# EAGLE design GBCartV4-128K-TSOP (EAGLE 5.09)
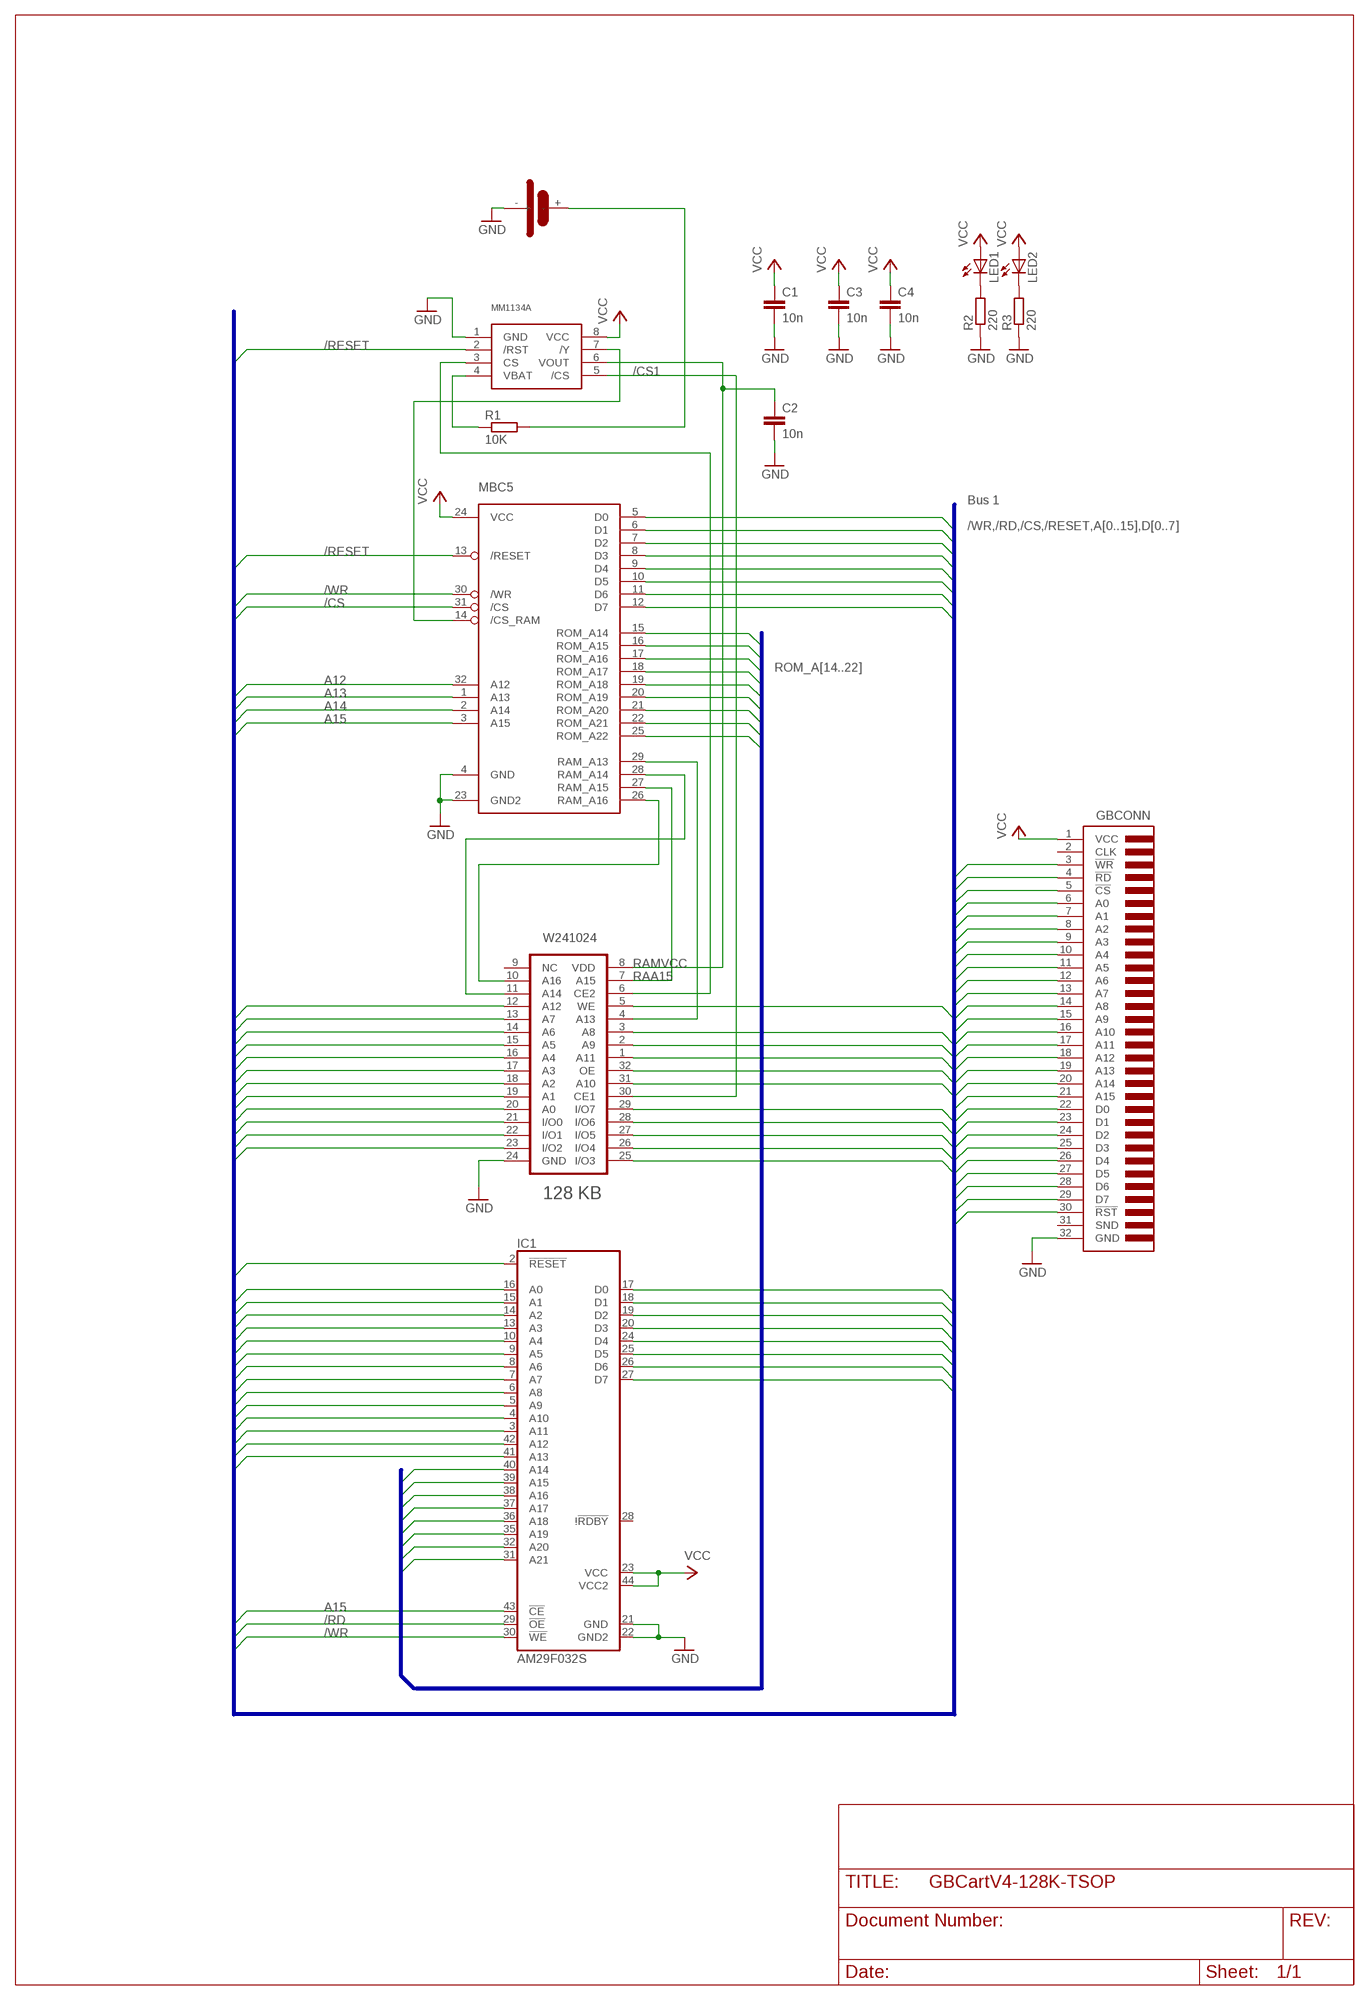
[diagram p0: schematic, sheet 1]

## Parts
C1  10n  C-EUC0805  [C0805]
C2  10n  C-EUC0805  [C0805]
C3  10n  C-EUC0805  [C0805]
C4  10n  C-EUC0805  [C0805]
GBCONN  GBCART-FULL  [GBCART]
IC1  AM29F032S  [SO44]
IC2  MBC5  [TQFP32-08]
IC3  W241024AT  [TSOP32]
IC4  MM1134A  [SOP08]
LED1  LEDCHIPLED_1206  [CHIPLED_1206]
LED2  LEDCHIPLED_1206  [CHIPLED_1206]
R1  10K  R-EU_R0805  [R0805]
R2  220  R-EU_R0805  [R0805]
R3  220  R-EU_R0805  [R0805]
U$1  CR1616  [CR1616]

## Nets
/CS [Signal]: GBCONN.5(!CS) IC2.31(/CS)
/CS1 [Signal]: IC3.30(CE1) IC4.5(/CS)
/CS2: IC3.6(CE2) IC4.3(CS)
/RD [Signal]: GBCONN.4(!RD) IC1.29(!OE) IC3.32(OE)
/RESET [Signal]: GBCONN.30(!RST) IC1.2(!RESET) IC2.13(/RESET) IC4.2(/RST)
/WR [Signal]: GBCONN.3(!WR) IC1.30(!WE) IC2.30(/WR) IC3.5(WE)
A0 [Signal]: GBCONN.6(A0) IC1.16(A0) IC3.20(A0)
A1 [Signal]: GBCONN.7(A1) IC1.15(A1) IC3.19(A1)
A2 [Signal]: GBCONN.8(A2) IC1.14(A2) IC3.18(A2)
A3 [Signal]: GBCONN.9(A3) IC1.13(A3) IC3.17(A3)
A4 [Signal]: GBCONN.10(A4) IC1.10(A4) IC3.16(A4)
A5 [Signal]: GBCONN.11(A5) IC1.9(A5) IC3.15(A5)
A6 [Signal]: GBCONN.12(A6) IC1.8(A6) IC3.14(A6)
A7 [Signal]: GBCONN.13(A7) IC1.7(A7) IC3.13(A7)
A8 [Signal]: GBCONN.14(A8) IC1.6(A8) IC3.3(A8)
A9 [Signal]: GBCONN.15(A9) IC1.5(A9) IC3.2(A9)
A10 [Signal]: GBCONN.16(A10) IC1.4(A10) IC3.31(A10)
A11 [Signal]: GBCONN.17(A11) IC1.3(A11) IC3.1(A11)
A12 [Signal]: GBCONN.18(A12) IC1.42(A12) IC2.32(A12) IC3.12(A12)
A13 [Signal]: GBCONN.19(A13) IC1.41(A13) IC2.1(A13)
A14 [Signal]: GBCONN.20(A14) IC2.2(A14)
A15 [Signal]: GBCONN.21(A15) IC1.43(!CE) IC2.3(A15)
D0 [Signal]: GBCONN.22(D0) IC1.17(D0) IC2.5(D0) IC3.21(I/O0)
D1 [Signal]: GBCONN.23(D1) IC1.18(D1) IC2.6(D1) IC3.22(I/O1)
D2 [Signal]: GBCONN.24(D2) IC1.19(D2) IC2.7(D2) IC3.23(I/O2)
D3 [Signal]: GBCONN.25(D3) IC1.20(D3) IC2.8(D3) IC3.25(I/O3)
D4 [Signal]: GBCONN.26(D4) IC1.24(D4) IC2.9(D4) IC3.26(I/O4)
D5 [Signal]: GBCONN.27(D5) IC1.25(D5) IC2.10(D5) IC3.27(I/O5)
D6 [Signal]: GBCONN.28(D6) IC1.26(D6) IC2.11(D6) IC3.28(I/O6)
D7 [Signal]: GBCONN.29(D7) IC1.27(D7) IC2.12(D7) IC3.29(I/O7)
GND: C1.2 C2.2 C3.2 C4.2 GBCONN.32(GND) IC1.21(GND) IC1.22(GND2) IC2.4(GND) IC2.23(GND2) IC3.24(GND) IC4.1(GND) R2.1 R3.1 U$1.-
N$3: LED1.C R2.2
N$4: IC4.4(VBAT) R1.1
N$5: R1.2 U$1.+
N$6: LED2.C R3.2
N$12 [Signal]: IC2.14(/CS_RAM) IC4.7(/Y)
RAA13: IC2.29(RAM_A13) IC3.4(A13)
RAA14: IC2.28(RAM_A14) IC3.11(A14)
RAA15: IC2.27(RAM_A15) IC3.7(A15)
RAA16: IC2.26(RAM_A16) IC3.10(A16)
RAMVCC: C2.1 IC3.8(VDD) IC4.6(VOUT)
ROM_A14 [Signal]: IC1.40(A14) IC2.15(ROM_A14)
ROM_A15 [Signal]: IC1.39(A15) IC2.16(ROM_A15)
ROM_A16 [Signal]: IC1.38(A16) IC2.17(ROM_A16)
ROM_A17 [Signal]: IC1.37(A17) IC2.18(ROM_A17)
ROM_A18 [Signal]: IC1.36(A18) IC2.19(ROM_A18)
ROM_A19 [Signal]: IC1.35(A19) IC2.20(ROM_A19)
ROM_A20 [Signal]: IC1.32(A20) IC2.21(ROM_A20)
ROM_A21 [Signal]: IC1.31(A21) IC2.22(ROM_A21)
ROM_A22: IC2.25(ROM_A22)
VCC: C1.1 C3.1 C4.1 GBCONN.1(VCC) IC1.23(VCC) IC1.44(VCC2) IC2.24(VCC) IC4.8(VCC) LED1.A LED2.A
Unconnected: GBCONN.2(CLK) GBCONN.31(SND) IC1.28(!!RDBY) IC3.9(NC)

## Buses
/WR,/RD,/CS,/RESET,A[0..15],D[0..7]
ROM_A[14..22]

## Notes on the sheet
- Bus 1

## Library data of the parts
C1-C4 = rcl:C-EU: CAPACITOR, European symbol
GBCONN = gameboy:GBCART
IC1 = gameboy:AM29F032S: 4-Megabit FLASH MEMORY (512 K x 8 bit/256 K x 16 Bit) 5 V-only
IC2 = gameboy:MBC5
IC3 = gameboy:W241024AT
IC4 = gameboy:MM1134A
LED1 LED2 = led:LED: LED
R1-R3 = rcl:R-EU_: RESISTOR, European symbol
U$1 = gameboy:CR1616

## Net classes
0 Supply: width 0.254 mm, clearance 0.254 mm
1 Signal: width 0.15 mm, clearance 0.15 mm

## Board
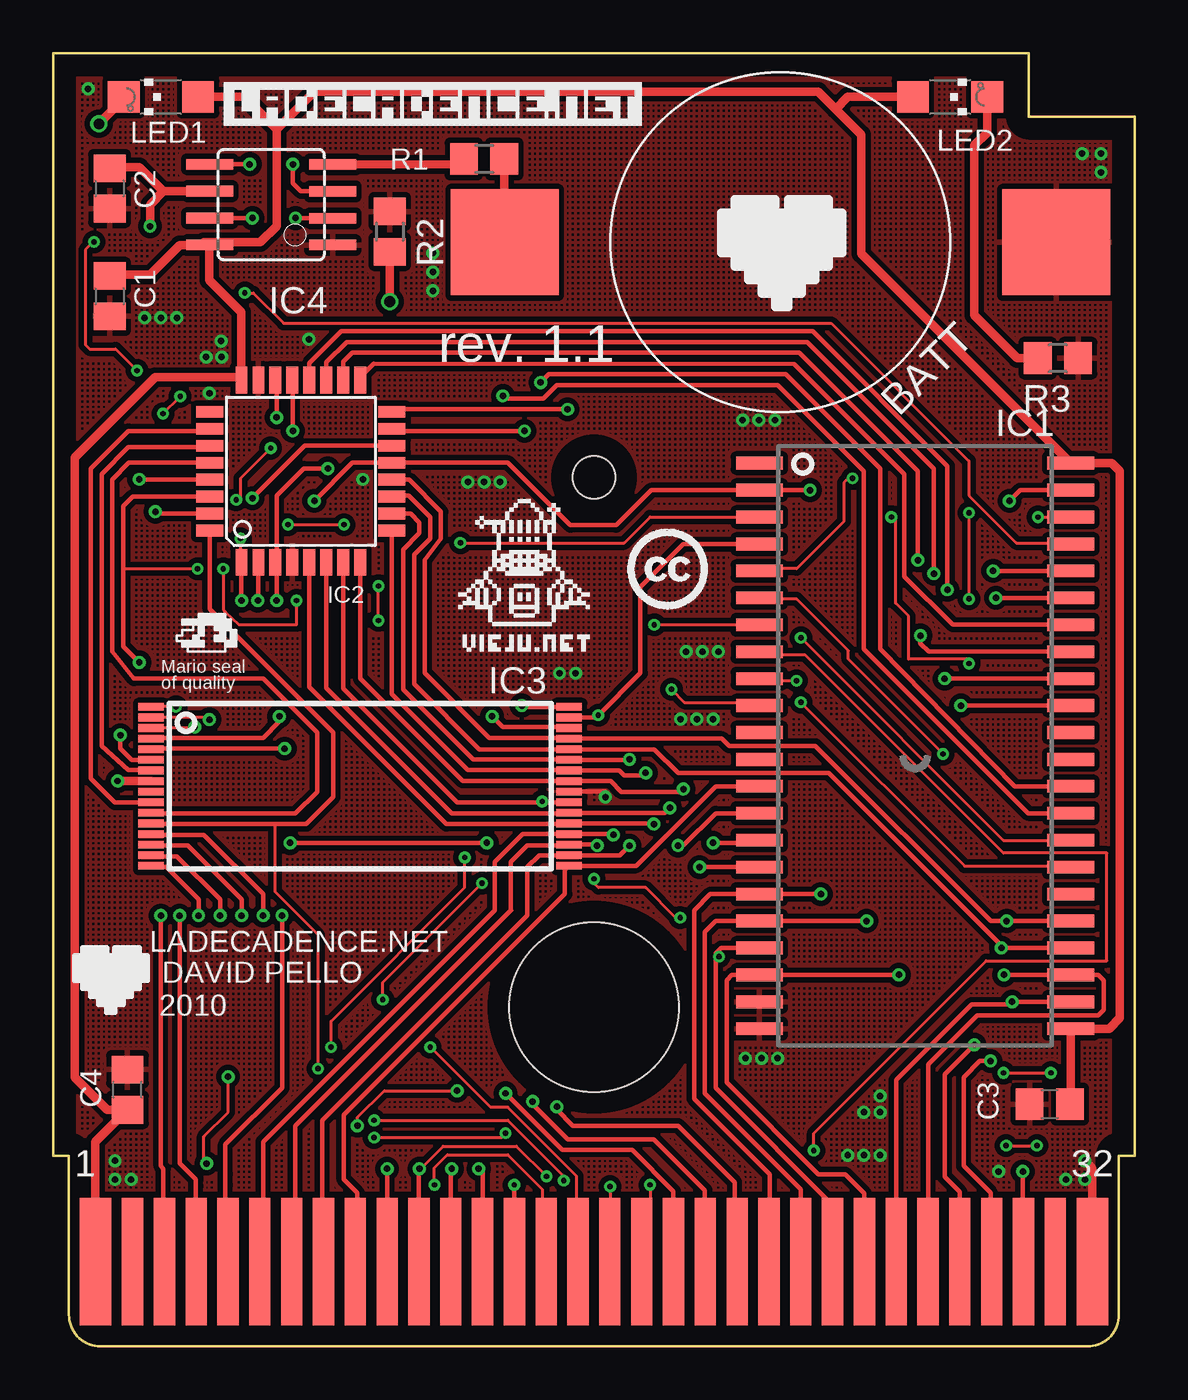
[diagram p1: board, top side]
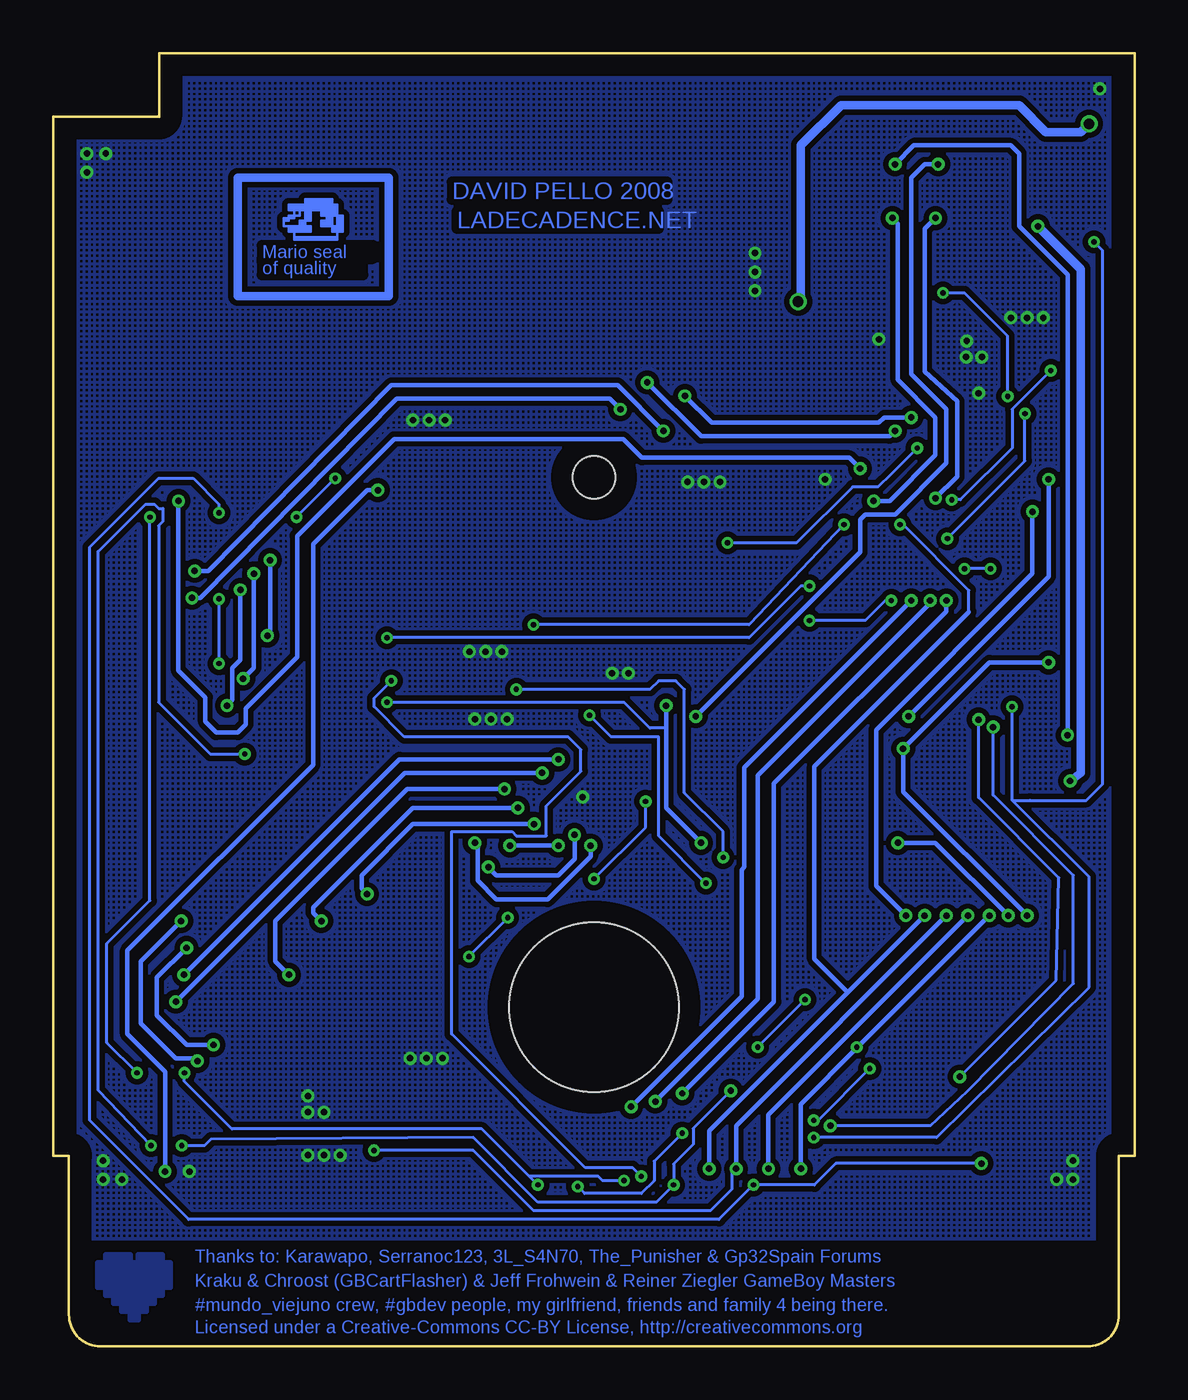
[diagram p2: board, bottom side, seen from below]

Size 51 x 61 mm. Coordinates in mm from the lower left corner, seen from the top.
Copper layers (1*16): Top 0.035mm / dielectric 1.5mm / Bottom 0.035mm
Design rules "default *": minimum track width 0.15mm, minimum drill 0.25mm, track to track 0.15mm, track to pad 0.15mm, pad to pad 0.15mm, via to via 0.15mm, smd to smd 8mil, copper to edge 40mil, drill to drill 8mil, minimum pad ring 6mil, minimum via ring 6mil, stop-mask expansion 4mil, vias tented up to drill 0mil, thermal gap 10mil

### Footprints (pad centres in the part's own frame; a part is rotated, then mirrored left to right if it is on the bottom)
C0805 = smd 1.3 x 1.5: 1 -0.95,0; 2 0.95,0
GBCART = smd 1.5 x 6: 1 -23.4,-25.21; 32 23.6,-25.21 | smd 1 x 6: 2 -21.65,-25.21; 3 -20.15,-25.21; 4 -18.65,-25.21; 5 -17.15,-25.21; 6 -15.65,-25.21; 7 -14.15,-25.21; 8 -12.65,-25.21; 9 -11.15,-25.21; 10 -9.65,-25.21; 11 -8.15,-25.21; 12 -6.65,-25.21; 13 -5.15,-25.21; 14 -3.65,-25.21; 15 -2.15,-25.21; 16 -0.65,-25.21; 17 0.85,-25.21; 18 2.35,-25.21; 19 3.85,-25.21; 20 5.35,-25.21; 21 6.85,-25.21; 22 8.35,-25.21; 23 9.85,-25.21; 24 11.35,-25.21; 25 12.85,-25.21; 26 14.35,-25.21; 27 15.85,-25.21; 28 17.35,-25.21; 29 18.85,-25.21; 30 20.35,-25.21; 31 21.85,-25.21 | hole 8: 0.1,-13.21 | hole 2: 0.1,11.79
SO44 = smd 0.6 x 2.2: 1 -13.335,-7.34; 2 -12.065,-7.34; 3 -10.795,-7.34; 4 -9.525,-7.34; 5 -8.255,-7.34; 6 -6.985,-7.34; 7 -5.715,-7.34; 8 -4.445,-7.34; 9 -3.175,-7.34; 10 -1.905,-7.34; 11 -0.635,-7.34; 12 0.635,-7.34; 13 1.905,-7.34; 14 3.175,-7.34; 15 4.445,-7.34; 16 5.715,-7.34; 17 6.985,-7.34; 18 8.255,-7.34; 19 9.525,-7.34; 20 10.795,-7.34; 21 12.065,-7.34; 22 13.335,-7.34; 23 13.335,7.34; 24 12.065,7.34; 25 10.795,7.34; 26 9.525,7.34; 27 8.255,7.34; 28 6.985,7.34; 29 5.715,7.34; 30 4.445,7.34; 31 3.175,7.34; 32 1.905,7.34; 33 0.635,7.34; 34 -0.635,7.34; 35 -1.905,7.34; 36 -3.175,7.34; 37 -4.445,7.34; 38 -5.715,7.34; 39 -6.985,7.34; 40 -8.255,7.34; 41 -9.525,7.34; 42 -10.795,7.34; 43 -12.065,7.34; 44 -13.335,7.34
TQFP32-08 = smd 1.27 x 0.559: 1 -4.293,2.8; 2 -4.293,2; 3 -4.293,1.2; 4 -4.293,0.4; 5 -4.293,-0.4; 6 -4.293,-1.2; 7 -4.293,-2; 8 -4.293,-2.8; 17 4.293,-2.8; 18 4.293,-2; 19 4.293,-1.2; 20 4.293,-0.4; 21 4.293,0.4; 22 4.293,1.2; 23 4.293,2; 24 4.293,2.8 | smd 0.559 x 1.27: 9 -2.8,-4.293; 10 -2,-4.293; 11 -1.2,-4.293; 12 -0.4,-4.293; 13 0.4,-4.293; 14 1.2,-4.293; 15 2,-4.293; 16 2.8,-4.293; 25 2.8,4.293; 26 2,4.293; 27 1.2,4.293; 28 0.4,4.293; 29 -0.4,4.293; 30 -1.2,4.293; 31 -2,4.293; 32 -2.8,4.293
TSOP32 = smd 1.2 x 0.36: 1 -9.85,3.75; 2 -9.85,3.25; 3 -9.85,2.75; 4 -9.85,2.25; 5 -9.85,1.75; 6 -9.85,1.25; 7 -9.85,0.75; 8 -9.85,0.25; 9 -9.85,-0.25; 10 -9.85,-0.75; 11 -9.85,-1.25; 12 -9.85,-1.75; 13 -9.85,-2.25; 14 -9.85,-2.75; 15 -9.85,-3.25; 16 -9.85,-3.75; 17 9.85,-3.75; 18 9.85,-3.25; 19 9.85,-2.75; 20 9.85,-2.25; 21 9.85,-1.75; 22 9.85,-1.25; 23 9.85,-0.75; 24 9.85,-0.25; 25 9.85,0.25; 26 9.85,0.75; 27 9.85,1.25; 28 9.85,1.75; 29 9.85,2.25; 30 9.85,2.75; 31 9.85,3.25; 32 9.85,3.75
SOP08 = smd 0.5 x 2.2: 1 -1.905,-2.9; 2 -0.645,-2.9; 3 0.625,-2.9; 4 1.895,-2.9; 5 1.905,2.9; 6 0.635,2.9; 7 -0.635,2.9; 8 -1.905,2.9
CHIPLED_1206 = smd 1.5 x 1.5: A 0,-1.75; C 0,1.75
R0805 = smd 1.3 x 1.5: 1 -0.95,0; 2 0.95,0
CR1616 = smd 5.08 x 5: + -13,0; - 13,0

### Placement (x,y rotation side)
C1  2.67,49.53 270 top
C2  2.67,54.61 270 top
C3  46.99,11.43 180 top
C4  3.51,12.11 90 top
GBCONN  25.4,29.21 0 top
IC1  40.64,28.32 270 top
IC2  11.68,41.28 90 top
IC3  14.48,26.42 0 top
IC4  10.29,53.85 90 top
LED1  5.08,58.93 90 top
LED2  42.29,58.93 270 top
R1  20.32,56.01 0 top
R2  15.88,52.58 270 top
R3  47.37,46.61 180 top
U$1  34.29,52.07 0 top
U$2  [MARIOSEAL]  38.61,52.58 0 top
U$3  [CC]  27.09,34.77 0 top
U$4  [VIEJU]  18.41,32.67 0 top
U$5  [CORAZON-SILK]  2.67,17.53 0 top
U$6  [LADECADENCE-TEXT-INV]  8.13,57.66 0 top
U$7  [MARIOSEAL-SILK]  4.7,30.48 0 top

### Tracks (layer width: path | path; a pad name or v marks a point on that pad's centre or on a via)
/CS  (via drill 0.3 pad 0.61)
  Top 0.203: IC2.31 4.92,39.28 v4.83,39.37 | GBCONN.5 8.13,4.12 8.13,7.62 8.13,8.13 8.13,9.53 10.79,12.19 v10.79,20.32
  Bottom 0.203: v4.83,39.37 4.83,36.45 12.19,29.08 12.19,21.72 v10.79,20.32
/CS1  (via drill 0.3 pad 0.61)
  Top 0.203: v9.27,55.75 IC4.5 | v20.7,29.72 21.21,29.21 24.28,29.21 IC3.30
  Bottom 0.203: v9.27,55.75 9.91,55.75 10.54,55.12 10.54,45.85 8.89,44.2 8.89,41.66 11.3,39.24 12.7,39.24 12.95,38.99 12.95,37.47 v20.7,29.72
/CS2  (via drill 0.3 pad 0.61)
  Top 0.203: IC4.3 13.18,54.48 11.68,54.48 11.3,54.86 v11.3,55.75 | v3.17,28.83 3.17,28.19 3.7,27.67 IC3.6
  Bottom 0.203: v11.3,55.75 10.41,56.64 5.84,56.64 5.46,56.26 5.46,52.83 3.17,50.55 v3.17,28.83
/RD  (via drill 0.25, 0.3 pad 0.61)
  Top 0.15: v35.26,30.38 42.98,22.66 47.85,22.66 IC1.29
  Top 0.203: GBCONN.4 6.73,7.58 6.73,7.87 5.97,8.64 v5.97,20.32 | v11.18,23.75 v20.45,23.75 | v22.1,30.23 22.16,30.17 IC3.32
  Bottom 0.15: v35.26,30.38 24.08,30.38 22.86,29.16 22.1,29.16
  Bottom 0.203: v5.97,20.32 9.4,23.75 v11.18,23.75 | v20.45,23.75 22.1,25.4 22.1,29.16 v22.1,30.23
/RESET  (via drill 0.3 pad 0.61)
  Top 0.203: IC4.2 13.18,53.21 v11.43,53.21 | v12.32,39.88 14.12,41.68 IC2.13 21.44,41.68 24.38,38.73 26.54,38.73 28.19,40.39 IC1.2 v35.69,40.39 | GBCONN.30 45.72,4.03 v45.72,8.26
  Bottom 0.203: v11.43,53.21 11.18,52.96 11.18,45.59 9.4,43.82 9.4,42.04 11.56,39.88 v12.32,39.88 | v45.72,8.26 45.72,12.95 47.5,14.73 47.5,18.67 38.73,27.43 38.73,37.85 36.2,40.39 v35.69,40.39
/WR  (via drill 0.25, 0.3 pad 0.61)
  Top 0.15: v35.26,33.43 44.81,23.88 IC1.30 | v15.34,34.24 v15.34,35.87 | v11.48,35.18 11.48,34.04 8.76,34.04 8.13,34.65 8.03,34.77 v8.03,36.68 | 3.3,36.68 v6.81,36.68
  Top 0.203: IC2.30 3.75,40.08 3.3,39.62 3.3,36.68 3.3,33.02 v4.06,32.26 | v10.92,28.19 4.66,28.19 IC3.5 | GBCONN.3 5.21,4.04 5.21,8.38 5.08,8.51 v5.08,20.32
  Bottom 0.15: v35.26,33.43 18.19,33.43 15.75,35.87 v15.34,35.87 | v15.34,34.24 12.7,34.24 11.76,35.18 v11.48,35.18 | v6.81,36.68 v8.03,36.68
  Bottom 0.203: v4.06,32.26 6.86,32.26 v10.92,28.19 10.92,26.16 v5.08,20.32
A0  (via drill 0.3 pad 0.61)
  Top 0.203: GBCONN.6 9.91,4.16 9.91,9.65 20.83,20.57 20.83,22.86 22.13,24.17 IC3.20 26.38,24.17 v26.42,24.13 | v30.48,22.61 IC1.16
  Bottom 0.203: v26.42,24.13 26.42,22.99 27.18,22.23 30.1,22.23 v30.48,22.61
A1  (via drill 0.3 pad 0.61)
  Top 0.203: GBCONN.7 11.37,4 11.43,4.06 11.43,10.41 21.59,20.57 21.59,22.86 22.35,23.62 24.28,23.62 IC3.19 25.61,23.67 v25.65,23.62 | v31.11,23.75 33.17,23.75 IC1.15
  Bottom 0.203: v25.65,23.62 25.65,23.11 27.69,21.08 30.1,21.08 30.99,21.97 30.99,23.62 v31.11,23.75
A2  (via drill 0.3 pad 0.61)
  Top 0.203: GBCONN.8 12.95,4.2 12.95,5.33 12.7,5.59 12.7,10.67 22.35,20.32 22.35,22.61 22.91,23.17 IC3.18 26.72,23.17 v27.18,23.62 | v29.46,23.62 29.72,23.62 31.24,25.15 IC1.14
  Bottom 0.203: v27.18,23.62 v29.46,23.62
A3
  Top 0.203: GBCONN.9 14.41,4 14.48,4.06 14.48,4.45 14.35,4.57 14.35,7.24 13.72,7.87 13.72,10.92 24.13,21.34 24.13,22.47 IC3.17 27.49,22.67 31.24,26.42 IC1.13
A4  (via drill 0.25, 0.3 pad 0.61)
  Top 0.15: v29.16,30.99 29.77,30.38 33.22,30.38 IC1.10 | v19.41,23.06 19.41,21.64 13.11,15.34 v13.11,14.12
  Top 0.203: GBCONN.10 v15.75,8.38 | v6.86,20.32 6.86,21.08 5.33,22.61 4.69,22.61 IC3.16
  Bottom 0.15: v29.16,30.99 22.86,30.99 22.45,31.39 21.64,31.39 21.23,30.99 21.23,26.11 19.41,24.28 v19.41,23.06 | 13.08,14.1 v13.11,14.12
  Bottom 0.203: v15.75,8.38 15.75,11.43 13.08,14.1 v6.86,20.32
A5  (via drill 0.25, 0.3 pad 0.61)
  Top 0.15: v35.05,31.39 33.43,31.39 IC1.9 | v23.27,8.03 21.84,9.45 18.39,9.45 17.37,8.43 v17.27,8.38
  Top 0.203: GBCONN.11 17.25,8.36 v17.27,8.38 | v7.87,20.32 7.87,21.08 5.84,23.11 4.68,23.11 IC3.15
  Bottom 0.15: v35.05,31.39 35.87,30.58 35.87,30.18 34.44,28.75 26.72,28.75 26.11,28.14 26.11,27.13 27.74,25.5 27.74,24.08 29.16,24.08 29.36,24.28 32.21,24.28 32.21,14.73 25.91,8.43 23.67,8.43 v23.27,8.03
  Bottom 0.203: v17.27,8.38 17.27,10.92 v7.87,20.32
A6  (via drill 0.25, 0.3 pad 0.61)
  Top 0.15: v35.87,9.25 35.87,10.06 43.99,18.19 49.68,18.19 49.68,23.27 44.81,23.27 35.46,32.61 33.43,32.61 IC1.8
  Top 0.203: GBCONN.12 18.75,8.08 v18.8,8.38 | v8.89,20.32 8.89,21.08 6.35,23.62 4.67,23.62 IC3.14
  Bottom 0.15: v35.87,9.25 31.19,9.25 28.35,6.4 20.02,6.4 19,7.42 19,8.43 18.8,8.64
  Bottom 0.203: v18.8,8.38 18.8,8.64 18.8,10.41 v8.89,20.32
A7  (via drill 0.25, 0.3 pad 0.61)
  Top 0.15: v11.07,38.76 v13.72,38.76 | v28.35,34.04 IC1.7
  Top 0.203: GBCONN.13 20.25,8.2 v20.07,8.38 | v9.91,20.32 9.91,21.34 7.11,24.13 4.66,24.13 IC3.13
  Bottom 0.15: v28.35,34.04 18.19,34.04 v13.72,38.76 | v11.07,38.76 10.92,38.76 7.82,35.66 7.82,34.65 | 12.88,17.35 12.9,17.37
  Bottom 0.203: v20.07,8.38 20.07,10.16 13.53,16.7 | 13.53,16.7 12.88,17.35 v9.91,20.32 | 7.82,34.65 15.11,27.36 15.11,18.29 13.53,16.7
A8  (via drill 0.25, 0.3 pad 0.61)
  Top 0.15: v41.96,27.94 37.49,32.41 37.49,32.82 35.05,35.26 33.43,35.26 IC1.6 | v44.93,9.47 v46.38,9.47 | v21.74,7.62 v21.75,7.62
  Top 0.152: IC3.3 6.64,29.17 v6.68,29.21 | v19.05,12.07 15.62,12.07 14.35,10.8 v14.35,10.41
  Top 0.203: v21.75,7.62 GBCONN.14
  Bottom 0.15: v41.96,27.94 43.59,27.94 46.02,30.38 46.02,38.71 45.82,38.91 45.82,39.52 46.02,39.52 46.23,39.73 46.63,39.73 48.87,37.49 48.87,12.09 v46.38,9.47 | v44.93,9.47 43.87,9.47 43.56,9.78 31.19,9.86 28.14,6.81 22.55,6.81 v21.74,7.62
  Bottom 0.152: v6.68,29.21 6.68,26.01 2.9,22.23 2.9,17.12 7.87,12.07 9.65,10.41 v14.35,10.41 | v21.74,7.62 21.74,8.61 20.83,9.53 20.83,10.29 v19.05,12.07
A9  (via drill 0.25, 0.3 pad 0.61)
  Top 0.15: v37.69,40.95 37.49,40.95 37.29,40.74 37.29,38.91 35.05,36.68 33.43,36.68 IC1.5 | v39.52,39.12 39.73,39.12 39.73,35.05 40.34,34.44 40.34,32.41 43.18,32.41 v43.18,32.21 | v43.18,39.32 v43.18,35.26 | v17.98,7.62 17.98,8.43 18.59,9.04 21.44,9.04 23.06,7.42 23.06,4.17 GBCONN.15
  Top 0.152: IC3.2 7.27,29.67 v7.37,29.57 | v8.26,12.73 8.26,11.05 7.11,9.91 7.11,8.76 v7.24,8.64
  Top 0.203: IC3.2 4.6,29.64
  Bottom 0.15: v43.18,35.26 v43.18,32.21 | v43.18,39.32 43.18,39.73 44.4,40.95 46.02,40.95 49.28,37.69 49.28,10.67 44.6,5.99 19.61,5.99 v17.98,7.62
  Bottom 0.152: v7.37,29.57 7.37,25.88 3.58,22.1 3.71,17.27 v8.26,12.73 | v7.24,8.64 14.1,8.64 15.11,7.62 v17.98,7.62 | v39.52,39.12 v37.69,40.95
A10  (via drill 0.25)
  Top 0.15: v17.78,14.12 20.62,11.28 21.44,11.28 24.69,8.03 24.69,4.17 GBCONN.16 | v15.54,16.36 15.54,17.17 v20.22,21.84
  Top 0.203: IC3.31 25.6,29.67 v25.7,29.77 27.69,31.75 27.69,35.81 29.72,37.85 IC1.4
  Bottom 0.15: v17.78,14.12 v15.54,16.36 | v20.22,21.84 22.45,24.08 22.45,28.75 24.69,28.75 v25.7,29.77
A11  (via drill 0.25)
  Top 0.15: v5.79,30.18 4.78,30.18 IC3.1 | v15.14,9.86 21.13,9.86 v21.34,10.06 | v26.26,7.54 26.26,4.9 26.11,4.17 GBCONN.17 | v19.2,37.9 26.92,37.9 28.14,39.12 IC1.3 | v10.26,42.37 8.84,40.95 8.84,39.93 v8.64,39.93 | v3.96,46.03 2.95,47.04 1.73,47.04 1.52,47.24 1.52,51.71 v1.93,52.09
  Bottom 0.15: v5.79,30.18 5.79,25.76 2.16,22.15 2.16,16.94 9.35,9.86 v15.14,9.86 | v21.34,10.06 22.66,8.74 22.66,7.82 23.27,7.21 25.93,7.21 v26.26,7.54 | v19.2,37.9 15.95,37.9 13.31,40.54 12.12,40.54 11.48,41.15 v10.26,42.37 | v8.64,39.93 8.23,39.93 5.79,42.37 5.79,44.2 v3.96,46.03 | v1.93,52.09 1.52,51.69 1.52,26.52 2.29,25.76 4.95,25.76
  Bottom 0.152: 5.79,25.76 4.95,25.76
A12  (via drill 0.25)
  Top 0.15: v44.81,12.9 v47.04,12.9 | v28.14,7.62 28.14,4.37 27.94,4.17 GBCONN.18 | v46.43,39.12 IC1.42 | v12.5,13.11 12.5,19.41 10.46,21.44 10.46,24.64 | v15.14,10.67 21.44,10.67 24.08,8.03 v24.08,7.82
  Top 0.203: IC2.32 7.39,34.77 13.21,28.96 13.21,25.91 11.94,24.64 10.46,24.64 4.66,24.64 IC3.12
  Bottom 0.15: v46.43,39.12 46.43,21.03 48.46,19 48.46,14.33 v47.04,12.9 | v44.81,12.9 44.81,12.5 42.57,10.26 30.79,10.26 28.55,8.03 | 28.55,8.03 v28.14,7.62 | v12.5,13.11 14.94,10.67 v15.14,10.67 | v24.08,7.82 25.09,7.82 25.3,8.03 28.55,8.03
A13  (via drill 0.25, 0.3 pad 0.61)
  Top 0.15: v9.04,49.68 9.45,49.68 10.87,48.26 36.68,48.26 43.18,41.76 43.18,40.13 45.41,37.9 47.85,37.9 IC1.41 | v5.18,43.99 v5.99,44.81 | v8.84,38.1 8.84,37.08 IC2.1
  Top 0.203: IC2.1 v8.88,35.19 v8.89,35.18 | GBCONN.19 29.25,7.33 27.3,9.27 24,9.27 v21.34,11.94
  Bottom 0.15: v9.04,49.68 8.03,49.68 5.99,47.65 v5.99,44.81 | v5.18,43.99 5.18,41.76 v8.84,38.1
  Bottom 0.203: v8.89,35.18 8.89,34.67 17.02,26.54 17.02,16.26 v21.34,11.94
A14  (via drill 0.3 pad 0.61)
  Top 0.203: IC2.2 9.68,35.21 v9.65,35.18 | GBCONN.20 30.73,4.02 30.73,7.37 28.32,9.78 24.26,9.78 22.61,11.43 v22.61,11.56
  Bottom 0.203: v9.65,35.18 9.65,35.05 17.78,26.92 17.78,16.38 v22.61,11.56
A15  (via drill 0.3 pad 0.25, 0.3 pad 0.61)
  Top 0.203: v10.54,35.18 10.54,36.98 IC2.3 10.54,37.04 10.54,40.13 11.81,41.4 v12.95,41.4 | GBCONN.21 32.13,4.12 32.13,7.75 29.46,10.41 24.51,10.41 23.75,11.18 v23.75,11.3 | v45.09,39.88 45.59,40.39 IC1.43
  Bottom 0.203: v10.54,35.18 18.41,27.31 18.41,22.61 18.54,22.48 18.54,16.51 v23.75,11.3 | v12.95,41.4 13.46,41.91 23.24,41.91 24.13,42.8 34.92,42.8 39.5,38.23 39.5,32.51 41.91,30.1 41.91,29.34 42.29,28.96 43.31,28.96 43.81,29.46 43.81,30.61 45.09,31.88 v45.09,39.88
D0  (via drill 0.3 pad 0.61)
  Top 0.203: GBCONN.22 33.78,4 33.78,8.13 30.23,11.68 30.23,20.57 30.99,21.34 IC1.17 v36.2,21.34 | IC2.5 12.08,31.1 18.54,24.64 24.3,24.64 IC3.21 28.29,24.67 v28.32,24.64
  Bottom 0.203: v28.32,24.64 34.04,24.64 36.45,22.23 36.45,21.59 v36.2,21.34
D1  (via drill 0.3 pad 0.61)
  Top 0.203: GBCONN.23 35.25,7.42 30.73,11.94 30.73,19.56 31.24,20.07 IC1.18 v38.35,20.07 | IC2.6 12.88,31.06 18.8,25.15 24.31,25.15 IC3.22 28.85,25.17 v29.08,25.4
  Bottom 0.203: v29.08,25.4 34.04,25.4 38.73,20.7 38.73,20.45 v38.35,20.07
D2  (via drill 0.25)
  Top 0.15: v25.5,22.05 25.5,21.84 25.7,21.64 27.94,21.64 29.36,20.22 v29.57,20.22 | v31.39,18.39 31.24,18.39 31.19,18.39 | v23.06,25.71 23.06,25.65
  Top 0.203: GBCONN.24 37,6.43 31.24,12.19 31.24,18.39 31.24,18.54 31.5,18.8 IC1.19 | IC2.7 13.68,31.02 19.05,25.65 23.06,25.65 24.32,25.65 IC3.23
  Bottom 0.15: v23.06,25.71 23.06,24.49 v25.5,22.05 | v31.39,18.39 v29.57,20.22
D3  (via drill 0.3 pad 0.61)
  Top 0.203: GBCONN.25 38.25,7.22 37.34,8.13 36.07,8.13 31.75,12.45 31.75,17.27 32,17.53 IC1.20 v39.88,17.53 | IC2.8 14.48,31.49 19.3,26.67 IC3.25 26.29,26.67 26.8,26.16 29.59,26.16 v29.72,26.29
  Bottom 0.203: v29.72,26.29 34.29,26.29 40.51,20.07 40.51,18.16 v39.88,17.53
D4  (via drill 0.3 pad 0.61)
  Top 0.203: IC2.9 15.98,30.76 19.56,27.18 24.32,27.18 IC3.26 26.68,27.17 26.92,26.92 27.81,26.92 v27.94,27.05 | IC1.24 v45.21,16.26 45.09,16.13 43.31,16.13 39.75,12.57 GBCONN.26
  Bottom 0.203: v27.94,27.05 34.42,27.05 v45.21,16.26
D5  (via drill 0.3 pad 0.61)
  Top 0.203: IC2.10 16.86,39.28 17.27,38.86 17.27,38.35 16.51,37.59 16.51,30.99 19.81,27.69 24.31,27.69 IC3.27 27.16,27.67 v27.18,27.69 | v44.83,17.53 IC1.25 49.28,17.53 49.53,17.27 49.53,15.88 49.28,15.62 43.56,15.62 41.25,13.31 GBCONN.27
  Bottom 0.203: v27.18,27.69 34.67,27.69 v44.83,17.53
D6  (via drill 0.3 pad 0.61)
  Top 0.203: IC2.11 16.03,40.13 16.76,40.13 17.78,39.12 17.78,38.1 17.02,37.34 17.02,31.24 20.09,28.17 IC3.28 28.35,28.17 29.46,27.05 36.58,27.05 44.83,18.8 | GBCONN.28 42.75,7.29 42.04,8 42.04,12.83 v43.43,14.22 | v44.7,18.8 44.83,18.8 | 44.83,18.8 IC1.26
  Bottom 0.203: v43.43,14.22 44.7,14.22 46.1,15.62 46.1,17.4 v44.7,18.8
D7  (via drill 0.3 pad 0.61)
  Top 0.203: GBCONN.29 44.45,4 44.45,5.59 44.2,5.84 44.2,7.24 42.93,8.51 42.93,12.7 43.69,13.46 v44.2,13.46 | IC2.12 16.78,40.88 18.29,39.37 18.29,38.1 17.53,37.08 17.53,31.75 20.57,28.7 24.29,28.7 IC3.29 31.53,28.67 31.88,28.32 35.94,28.32 44.2,20.07 v44.96,20.07 IC1.27
  Bottom 0.203: v44.2,13.46 44.32,13.59 45.21,13.59 46.86,15.24 46.86,18.16 v44.96,20.07
GND  (via drill 0.3 pad 0.61)
  Top 0.203: IC2.4 11.33,36.98 11.43,37.08 | v26.04,25.91 26.03,26.17 IC3.24
  Top 0.406: GBCONN.32 49,8.4 v48.64,8.76
  other vias: 47.75,7.87 48.64,7.87 1.65,59.31 1.65,59.31 1.65,59.31 2.92,8.76 2.92,7.87 3.68,7.87 49.4,55.37 48.51,56.26 49.4,56.26 17.91,49.78 17.91,50.67 17.91,51.56 12.06,47.5 34.04,43.69 33.27,43.69 32.51,43.69 21.08,40.77 20.32,40.77 19.56,40.77 14.61,40.89 4.32,48.51 5.08,48.51 5.84,48.51 7.37,44.96 32.64,13.59 33.4,13.59 34.16,13.59 38.99,11.81 38.23,11.05 38.99,11.05 37.47,9.02 38.23,9.02 38.99,9.02 44.58,8.26 23.88,31.75 24.64,31.75 31.37,32.77 30.61,32.77 29.84,32.77 31.11,29.59 30.35,29.59 29.59,29.59 7.95,46.66 7.92,47.42 7.21,46.66
  pour Top (hatched): 0.38,60.58 45.97,60.96 45.97,57.91 50.67,57.91 50.67,7.37 0.25,7.37 0.25,7.62 0.38,7.62
  pour Bottom (hatched): 0.25,60.83 45.85,61.09 45.85,60.96 46.1,60.96 46.1,58.04 50.93,58.04 50.93,4.95 50.8,5.08 0,5.08 0.25,5.33
N$3  (via drill 0.5 pad 0.3)
  Top 0.406: LED1.C 3.43,58.93 v2.16,57.66 | v15.88,49.28 R2.2
  Bottom 0.406: v2.16,57.66 2.54,57.28 4.19,57.28 5.46,58.55 13.84,58.55 15.75,56.64 15.75,49.4 v15.88,49.28
N$4
  Top 0.406: R1.1 19.04,55.75 IC4.4
N$5
  Top 0.406: R1.2 21.27,52.09 U$1.+
N$6
  Top 0.406: LED2.C 44.04,57.25 43.43,56.64 43.43,48.64 45.47,46.61 R3.2
N$10
  pour Bottom: 46.99,3.94 47.37,3.94 47.37,4.32 48.51,4.32 48.51,3.94 48.9,3.94 48.9,2.79 48.51,2.79 48.51,2.41 48.13,2.41 48.13,2.03 47.75,2.03 47.75,1.65 47.37,1.65 47.37,1.27 46.99,1.27 46.99,1.65 46.61,1.65 46.61,2.03 46.23,2.03 46.23,2.41 45.85,2.41 45.85,2.79 45.47,2.79 45.47,3.94 45.85,3.94 45.85,4.32 46.99,4.32
N$11
  Bottom 0.406: 42.29,49.53 42.29,55.12 35.18,55.12 35.18,49.53 42.29,49.53
N$12  (via drill 0.3 pad 0.61)
  Top 0.203: v9.4,53.21 IC4.7 | v9.4,40.01 11.87,42.48 IC2.14
  Bottom 0.203: v9.4,53.21 9.91,52.71 9.91,45.97 8.38,44.58 8.38,41.02 v9.4,40.01
RAA13  (via drill 0.3 pad 0.61)
  Top 0.203: IC2.29 4.08,40.88 v4.06,40.89 | v10.67,29.72 10.67,29.46 9.91,28.7 4.66,28.7 IC3.4
  Bottom 0.203: v4.06,40.89 4.06,36.32 v10.67,29.72
RAA14
  Top 0.203: IC2.28 3.58,41.68 2.79,40.89 2.79,32.77 3.81,31.5 9.91,31.5 12.45,28.96 12.45,26.16 11.43,25.15 4.65,25.15 IC3.11
RAA15
  Top 0.203: IC2.27 7.39,42.44 7.37,42.42 3.56,42.42 2.29,41.15 2.29,28.32 3.56,27.18 4.62,27.18 IC3.7
RAA16
  Top 0.203: IC2.26 7.39,43.21 7.37,43.18 3.56,43.18 1.78,41.4 1.78,26.8 2.92,25.65 4.62,25.65 IC3.10
RAMVCC  (via drill 0.3 pad 0.61)
  Top 0.406: 5.21,54.48 IC4.6 | 5.21,54.48 4.06,55.63 2.73,55.63 C2.1 | 5.21,54.48 4.57,53.85 v4.57,52.83 | v3.05,26.67 3.42,26.67 IC3.8
  Bottom 0.406: v4.57,52.83 2.54,50.8 2.54,27.05 v3.05,26.67
ROM_A14  (via drill 0.3 pad 0.61)
  Top 0.203: v44.32,36.58 IC1.40 | v22.23,43.18 16.07,43.18 IC2.15
  Bottom 0.203: v44.32,36.58 43.69,36.58 35.05,45.34 24.38,45.34 v22.23,43.18
ROM_A15  (via drill 0.3 pad 0.61)
  Top 0.203: v44.45,35.31 IC1.39 | v24.26,44.2 16.1,44.2 IC2.16
  Bottom 0.203: v44.45,35.31 44.07,35.31 34.8,44.7 24.77,44.7 v24.26,44.2
ROM_A16
  Top 0.203: IC2.17 14.48,45.73 15.11,46.36 34.95,46.33 40.13,41.15 40.13,36.32 42.42,34.04 IC1.38
ROM_A17  (via drill 0.3 pad 0.61)
  Top 0.203: IC2.18 13.68,46.45 14.1,46.86 35.18,46.86 40.77,41.28 v40.77,37.08 | v40.89,33.53 40.89,33.15 41.27,32.77 IC1.37
  Bottom 0.203: v40.77,37.08 40.77,33.66 v40.89,33.53
ROM_A18  (via drill 0.3 pad 0.61)
  Top 0.203: IC2.19 12.88,46.41 13.84,47.37 35.56,47.37 41.53,41.4 v41.53,36.45 | v42.04,31.5 IC1.36
  Bottom 0.203: v41.53,36.45 41.53,32 v42.04,31.5
ROM_A19  (via drill 0.3 pad 0.61)
  Top 0.203: IC2.20 12.08,46.37 13.59,47.88 35.81,47.88 42.16,41.53 v42.16,35.69 | v42.8,30.23 IC1.35
  Bottom 0.203: v42.16,35.69 42.16,32.39 42.55,32 42.55,30.48 v42.8,30.23
ROM_A20  (via drill 0.3 pad 0.61)
  Top 0.203: IC1.32 45.34,26.42 38.99,32.89 38.99,41.4 34.54,45.85 23.37,45.85 v22.99,45.47 | v11.3,43.18 11.3,45.55 IC2.21
  Bottom 0.203: v22.99,45.47 20.45,42.93 11.56,42.93 v11.3,43.18
ROM_A21  (via drill 0.3 pad 0.61)
  Top 0.203: IC1.31 45.97,25.15 38.23,32.89 38.23,41.28 34.16,45.34 23.75,45.34 23.11,44.7 21.34,44.7 v21.21,44.83 | v10.54,43.82 10.54,45.51 IC2.22
  Bottom 0.203: v21.21,44.83 19.94,43.56 12.06,43.56 11.81,43.82 v10.54,43.82
VCC
  Top 0.406: C1.1 2.73,50.55 4.57,50.55 5.97,51.94 IC4.8 7.37,51.92 7.37,51.82 | GBCONN.1 2,9.65 C4.1 2.56,11.16 1.02,12.7 1.02,41.91 4.83,45.72 8.73,45.72 IC2.24 8.88,48.77 7.37,50.29 7.37,51.82 | 7.37,51.82 7.11,52.07 9.78,52.07 10.54,52.83 10.54,57.4 | 10.54,57.4 12.32,59.18 36.07,59.18 36.89,58.36 | 36.89,58.36 38.1,57.15 38.1,51.54 IC1.44 49.91,41.66 50.29,41.28 50.29,15.49 49.78,14.99 IC1.23 47.98,11.47 C3.1 | LED2.A 37.47,58.93 36.89,58.36 | LED1.A 9.02,58.93 10.54,57.4

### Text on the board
Bottom: DAVID PELLO 2008 | LADECADENCE.NET | Thanks to: Karawapo, Serranoc123, 3L_S4N70, The_Punisher & Gp32Spain Forums | Kraku & Chroost (GBCartFlasher) & Jeff Frohwein & Reiner Ziegler GameBoy Masters | #mundo_viejuno crew, #gbdev people, my girlfriend, friends and family 4 being there. | Licensed under a Creative-Commons CC-BY License, http://creativecommons.org
tNames: rev. 1.1 | BATT | LADECADENCE.NET | DAVID PELLO | 2010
